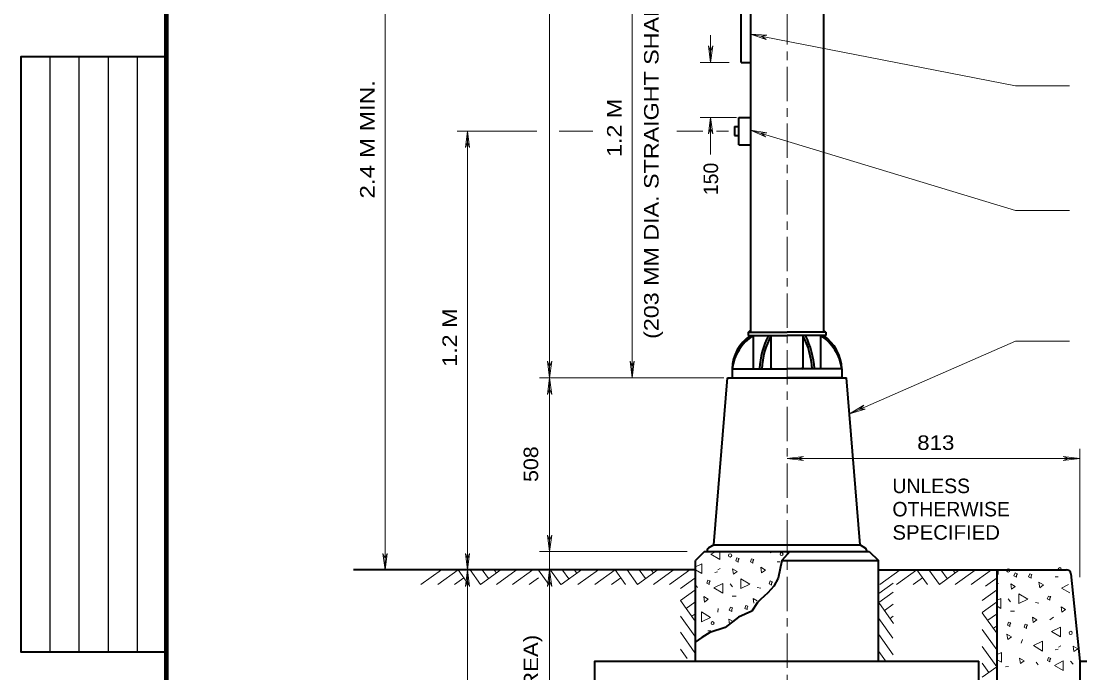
# Model space of a CAD drawing. Extents: x 312583 to 312853, y 144419 to 144586.
# Drawn here: x 312608.9 to 312664.4, y 144455.8 to 144490 of the extents above; entities that cross this region are included whole.
import ezdxf

# ---------------------------------------------------------------- set-up
doc = ezdxf.new("R2010")
doc.units = 0
doc.header["$LTSCALE"] = 0.3
doc.linetypes.add('LONG_DASH_SHORT_DASH', pattern=[9.9, 6, -1.2, 1.5, -1.2])
doc.layers.add('1', color=7, linetype='Continuous', lineweight=40)
doc.layers.add('2', color=7, linetype='Continuous', lineweight=13)

msp = doc.modelspace()

# ---------------------------------------------------------------- linework, layer by layer
at = {"layer": '1'}
for p, q in [((312647.0938, 144494.2759), (312647.0938, 144473.6679)), ((312650.9271, 144494.2759), (312650.9271, 144473.6679)), ((312646.6108, 144487.8053), (312646.6108, 144493.5553)), ((312646.6108, 144487.8053), (312647.0938, 144487.8053)), ((312646.4881, 144484.9303), (312647.0938, 144484.9303)), ((312646.4881, 144483.4966), (312646.4881, 144484.9303)), ((312646.2504, 144484.4549), (312646.2504, 144483.9719)), ((312646.2504, 144484.4549), (312646.4881, 144484.4549)), ((312646.2504, 144483.9719), (312646.4881, 144483.9719)), ((312646.4881, 144483.4966), (312647.0938, 144483.4966)), ((312646.9711, 144473.6679), (312649.0104, 144473.6679)), ((312646.9711, 144473.6679), (312646.9711, 144473.4916)), ((312651.0421, 144473.6679), (312649.0104, 144473.6679)), ((312651.0421, 144473.6679), (312651.0421, 144473.4916)), ((312646.9711, 144473.4916), (312649.0104, 144473.4916)), ((312647.2471, 144471.7513), (312647.2471, 144473.4916)), ((312648.1671, 144473.4916), (312648.1671, 144471.8126)), ((312651.0421, 144473.4916), (312649.0104, 144473.4916)), ((312649.8461, 144473.4916), (312649.8461, 144471.8126)), ((312650.7738, 144471.7513), (312650.7738, 144473.4916)), ((312646.1354, 144471.7513), (312649.0104, 144471.7513)), ((312646.1354, 144471.7513), (312646.1354, 144471.2759)), ((312651.8854, 144471.7513), (312649.0104, 144471.7513)), ((312651.8854, 144471.7513), (312651.8854, 144471.2759)), ((312645.1771, 144462.5283), (312645.8901, 144471.2759)), ((312645.8901, 144471.2759), (312652.1231, 144471.2759)), ((312646.1354, 144471.2759), (312649.0104, 144471.2759)), ((312651.8854, 144471.2759), (312649.0104, 144471.2759)), ((312652.8438, 144462.5283), (312652.1231, 144471.2759)), ((312645.1771, 144462.5283), (312644.8858, 144462.3443)), ((312645.1771, 144462.5283), (312652.8438, 144462.5283)), ((312652.8438, 144462.5283), (312653.1274, 144462.3443)), ((312644.6941, 144462.1679), (312644.2188, 144461.6926)), ((312644.6941, 144462.1679), (312653.3191, 144462.1679)), ((312653.3191, 144462.1679), (312653.8021, 144461.6926)), ((312644.2188, 144456.4179), (312644.2188, 144461.6926)), ((312648.7344, 144461.6926), (312653.8021, 144461.6926)), ((312653.8021, 144456.4179), (312653.8021, 144461.6926)), ((312644.2188, 144461.2096), (312626.2941, 144461.2096)), ((312653.8021, 144461.2096), (312663.6461, 144461.2096)), ((312660.0274, 144451.6263), (312660.0274, 144461.2096)), ((312663.8838, 144460.9949), (312664.3438, 144456.4179)), ((312664.3438, 144456.4179), (312664.3438, 144451.6263)), ((312664.3438, 144456.4179), (312717.6041, 144456.4179))]:
    msp.add_line(p, q, dxfattribs=at)
at = {"layer": '1', "lineweight": 25}
for p, q in [((312610.4087, 144456.901), (312610.4087, 144488.1192)), ((312611.9315, 144456.901), (312611.9315, 144488.1192)), ((312613.4543, 144456.901), (312613.4543, 144488.1192)), ((312614.9772, 144456.901), (312614.9772, 144488.1192)), ((312646.9711, 144473.6679), (312647.0938, 144473.7906)), ((312651.0421, 144473.6679), (312650.9271, 144473.7906))]:
    msp.add_line(p, q, dxfattribs=at)
at = {"layer": '1', "lineweight": 13}
for p, q in [((312660.0274, 144460.9949), (312660.0658, 144460.9643)), ((312660.0658, 144460.9643), (312660.0658, 144461.2096)), ((312663.0634, 144460.8416), (312663.2091, 144460.8493)), ((312660.0274, 144460.4583), (312660.0888, 144460.4966)), ((312660.6024, 144459.6916), (312660.7251, 144459.5383)), ((312660.0274, 144459.3083), (312660.2191, 144459.1933)), ((312662.0284, 144459.4999), (312662.2048, 144459.4616)), ((312660.7174, 144459.0399), (312660.9244, 144459.0476)), ((312662.9638, 144458.7333), (312662.7874, 144458.5953)), ((312661.3538, 144457.5526), (312661.2771, 144457.3763)), ((312663.0634, 144457.0159), (312663.2091, 144457.0466)), ((312663.2398, 144457.1539), (312663.3624, 144457.2229)), ((312660.0274, 144456.4946), (312660.2421, 144456.3643)), ((312662.0591, 144456.3643), (312662.1664, 144456.2263)), ((312663.8684, 144456.4179), (312663.9988, 144456.2646)), ((312660.4568, 144456.1266), (312660.6101, 144456.1419))]:
    msp.add_line(p, q, dxfattribs=at)
at = {"layer": '1', "lineweight": 158}
msp.add_lwpolyline([(312616.5, 144423.1446), (312616.5, 144585.0846), (312849, 144585.0846)], dxfattribs=at)
at = {"layer": '1', "lineweight": 35}
msp.add_lwpolyline([(312616.5, 144456.901), (312608.8858, 144456.901), (312608.8858, 144488.1192), (312616.5, 144488.1192)], dxfattribs=at)
at = {"layer": '1'}
for points in [[(312649.1638, 144462.1679), (312648.7344, 144461.6926), (312648.5428, 144460.7726), (312648.3128, 144460.3509), (312648.0061, 144460.0059), (312647.6228, 144459.6609), (312647.4694, 144459.5076), (312647.1628, 144459.0399), (312646.4651, 144458.7333), (312645.7751, 144458.1966), (312644.9624, 144457.9283), (312644.5408, 144457.6599), (312644.1958, 144457.4223)], [(312638.9441, 144439.1679), (312659.0691, 144439.1679), (312659.0691, 144456.4179)], [(312638.9441, 144439.1679), (312638.9441, 144456.4179), (312659.0691, 144456.4179)]]:
    msp.add_lwpolyline(points, dxfattribs=at)
at = {"layer": '1', "lineweight": 13}
for points in [[(312661.0318, 144460.9336), (312661.0778, 144461.0103), (312660.9628, 144461.0486), (312660.9014, 144460.8953), (312661.0318, 144460.8263)], [(312661.7984, 144460.8799), (312661.8444, 144460.9643), (312661.7294, 144460.9949), (312661.6681, 144460.8416), (312661.7984, 144460.7726)], [(312660.7788, 144460.1976), (312660.9704, 144460.3433), (312660.7328, 144460.4813)], [(312662.2508, 144460.2743), (312662.4501, 144460.4199), (312662.2124, 144460.5579)], [(312661.1621, 144459.9523), (312661.1621, 144459.4386), (312661.6298, 144459.6686)], [(312662.7798, 144459.7223), (312662.8258, 144459.8066), (312662.7108, 144459.8373), (312662.6494, 144459.6916), (312662.7798, 144459.6149)], [(312663.4161, 144458.9939), (312663.6078, 144459.1396), (312663.3778, 144459.2776)], [(312661.9134, 144458.4496), (312662.1051, 144458.5953), (312661.8751, 144458.7333)], [(312660.6868, 144458.3423), (312660.7328, 144458.4266), (312660.6178, 144458.4649), (312660.5564, 144458.3116), (312660.6868, 144458.2426)], [(312661.5608, 144458.2426), (312661.6068, 144458.3269), (312661.4918, 144458.3653), (312661.4304, 144458.2119), (312661.5608, 144458.1429)], [(312663.3394, 144457.6983), (312663.3394, 144458.2119), (312662.8718, 144457.9743)], [(312660.5718, 144457.5603), (312660.7634, 144457.7059), (312660.5334, 144457.8439)], [(312662.3964, 144456.9546), (312662.3964, 144457.4759), (312661.9288, 144457.2383)], [(312664.0448, 144456.9239), (312664.2441, 144457.0696), (312664.0064, 144457.2076)], [(312661.2388, 144456.2953), (312661.4304, 144456.4486), (312661.1928, 144456.5866)], [(312662.7874, 144456.4946), (312662.8334, 144456.5713), (312662.7184, 144456.6096), (312662.6571, 144456.4563), (312662.7874, 144456.3873)], [(312663.4851, 144455.9273), (312663.4851, 144456.4409), (312663.0174, 144456.2033)]]:
    msp.add_lwpolyline(points, close=True, dxfattribs=at)
for points in [[(312663.7534, 144460.4429), (312663.3931, 144460.2589), (312663.8224, 144460.0059)], [(312660.2191, 144459.1933), (312660.2191, 144459.7146), (312660.0274, 144459.6149)], [(312660.2421, 144456.3643), (312660.2421, 144456.8779), (312660.0274, 144456.7706)]]:
    msp.add_lwpolyline(points, dxfattribs=at)
for centre, radius in [((312663.2998, 144461.2478), 0.0784), ((312660.6003, 144461.1772), 0.0865), ((312663.8726, 144457.9049), 0.0865)]:
    msp.add_circle(centre, radius, dxfattribs=at)
at = {"layer": '1'}
for centre, radius, start, end in [((312648.3292, 144471.6731), 2.1986, 124.21849, 177.88724), ((312648.5437, 144471.4346), 2.4327, 122.28719, 172.4519), ((312652.0072, 144471.4976), 4.4452, 153.35491, 176.59885), ((312652.0072, 144471.4976), 4.3255, 152.55593, 176.59975), ((312646.007, 144471.4976), 4.3255, 3.40025, 27.44407), ((312646.007, 144471.4976), 4.4452, 3.40115, 26.64509), ((312649.4705, 144471.4346), 2.4327, 7.5481, 57.71281), ((312649.685, 144471.6731), 2.1986, 2.11276, 55.78151), ((312648.2284, 144471.814), 0.0599, 180, 270), ((312649.7857, 144471.814), 0.0599, 270, 0), ((312645.054, 144462.1708), 0.2396, 134.94464, 180), ((312652.9602, 144462.1708), 0.2396, 0, 45.05536), ((312663.6444, 144460.9729), 0.2396, 5.71059, 90)]:
    msp.add_arc(centre, radius, start, end, dxfattribs=at)
at = {"layer": '2', "linetype": 'LONG_DASH_SHORT_DASH'}
msp.add_line((312649.0104, 144438.2556), (312649.0104, 144579.5523), dxfattribs=at)
at = {"layer": '2'}
for p, q in [((312636.5751, 144471.2759), (312636.5751, 144564.8323)), ((312627.9501, 144461.2096), (312627.9501, 144507.2096)), ((312640.8914, 144471.2759), (312640.8914, 144494.2759)), ((312645.0084, 144487.8053), (312645.0084, 144489.2466)), ((312660.9781, 144486.5786), (312647.0938, 144489.2926)), ((312647.0938, 144489.2926), (312647.9218, 144489.0166)), ((312647.0938, 144489.2926), (312647.9601, 144489.2313)), ((312647.9601, 144489.2313), (312647.6688, 144489.1776)), ((312647.9218, 144489.0166), (312647.6688, 144489.1776)), ((312644.9011, 144488.6716), (312645.0084, 144488.3956)), ((312645.0084, 144487.8053), (312644.9011, 144488.6716)), ((312645.1158, 144488.6716), (312645.0084, 144488.3956)), ((312645.0084, 144487.8053), (312645.1158, 144488.6716)), ((312645.9744, 144487.8053), (312644.4641, 144487.8053)), ((312663.8071, 144486.5786), (312660.9781, 144486.5786)), ((312646.3578, 144484.9303), (312644.4641, 144484.9303)), ((312645.0084, 144484.9303), (312644.9011, 144484.0639)), ((312645.0084, 144482.9753), (312645.0084, 144484.9303)), ((312645.0084, 144484.9303), (312645.1158, 144484.0639)), ((312635.9004, 144484.2096), (312631.7221, 144484.2096)), ((312632.2664, 144484.2096), (312632.1591, 144483.3433)), ((312632.2664, 144461.2096), (312632.2664, 144484.2096)), ((312632.2664, 144484.2096), (312632.3738, 144483.3433)), ((312638.8444, 144484.2096), (312637.0734, 144484.2096)), ((312644.5944, 144484.2096), (312643.2374, 144484.2096)), ((312644.9011, 144484.0639), (312645.0084, 144484.3399)), ((312645.1158, 144484.0639), (312645.0084, 144484.3399)), ((312645.9514, 144484.2096), (312645.3151, 144484.2096)), ((312660.9781, 144480.0543), (312647.0938, 144484.2633)), ((312647.0938, 144484.2633), (312647.8911, 144483.9106)), ((312647.0938, 144484.2633), (312647.9524, 144484.1176)), ((312647.9524, 144484.1176), (312647.6534, 144484.0946)), ((312647.8911, 144483.9106), (312647.6534, 144484.0946)), ((312632.1591, 144483.3433), (312632.2664, 144483.6193)), ((312632.3738, 144483.3433), (312632.2664, 144483.6193)), ((312663.8071, 144480.0543), (312660.9781, 144480.0543)), ((312636.4678, 144472.1423), (312636.5751, 144471.8663)), ((312636.5751, 144471.2759), (312636.4678, 144472.1423)), ((312636.6824, 144472.1423), (312636.5751, 144471.8663)), ((312636.5751, 144471.2759), (312636.6824, 144472.1423)), ((312640.7841, 144472.1423), (312640.8914, 144471.8663)), ((312640.8914, 144471.2759), (312640.7841, 144472.1423)), ((312640.9988, 144472.1423), (312640.8914, 144471.8663)), ((312640.8914, 144471.2759), (312640.9988, 144472.1423)), ((312645.6984, 144471.2759), (312636.0461, 144471.2759)), ((312636.5751, 144471.2759), (312636.4678, 144470.4096)), ((312636.5751, 144462.1679), (312636.5751, 144471.2759)), ((312636.5751, 144471.2759), (312636.6824, 144470.4096)), ((312636.4678, 144470.4096), (312636.5751, 144470.6856)), ((312636.6824, 144470.4096), (312636.5751, 144470.6856)), ((312652.2764, 144469.3899), (312653.0278, 144469.8346)), ((312652.2764, 144469.3899), (312653.1121, 144469.6353)), ((312653.0278, 144469.8346), (312652.8208, 144469.6276)), ((312653.1121, 144469.6353), (312652.8208, 144469.6276)), ((312664.3438, 144460.8186), (312664.3438, 144467.5499)), ((312649.0104, 144467.0439), (312649.8768, 144467.1513)), ((312664.3438, 144467.0439), (312649.0104, 144467.0439)), ((312649.0104, 144467.0439), (312649.8768, 144466.9366)), ((312649.8768, 144467.1513), (312649.6008, 144467.0439)), ((312649.8768, 144466.9366), (312649.6008, 144467.0439)), ((312663.4774, 144467.1513), (312663.7534, 144467.0439)), ((312664.3438, 144467.0439), (312663.4774, 144467.1513)), ((312663.4774, 144466.9366), (312663.7534, 144467.0439)), ((312664.3438, 144467.0439), (312663.4774, 144466.9366)), ((312636.4678, 144463.0343), (312636.5751, 144462.7583)), ((312636.5751, 144462.1679), (312636.4678, 144463.0343)), ((312636.6824, 144463.0343), (312636.5751, 144462.7583)), ((312636.5751, 144462.1679), (312636.6824, 144463.0343)), ((312627.8428, 144462.0759), (312627.9501, 144461.7999)), ((312627.9501, 144461.2096), (312627.8428, 144462.0759)), ((312628.0574, 144462.0759), (312627.9501, 144461.7999)), ((312627.9501, 144461.2096), (312628.0574, 144462.0759)), ((312632.1591, 144462.0759), (312632.2664, 144461.7999)), ((312632.2664, 144461.2096), (312632.1591, 144462.0759)), ((312632.3738, 144462.0759), (312632.2664, 144461.7999)), ((312632.2664, 144461.2096), (312632.3738, 144462.0759)), ((312643.7818, 144462.1679), (312636.0461, 144462.1679)), ((312645.4914, 144461.7539), (312645.4914, 144462.1679)), ((312648.4891, 144461.6313), (312648.6348, 144461.6389)), ((312629.8284, 144460.4506), (312630.9018, 144461.2096)), ((312630.7101, 144460.4506), (312631.7834, 144461.2096)), ((312631.5918, 144460.4506), (312632.0748, 144460.7956)), ((312631.7834, 144461.2096), (312632.3201, 144460.4506)), ((312632.2664, 144461.2096), (312632.1591, 144460.3433)), ((312632.2664, 144439.1679), (312632.2664, 144461.2096)), ((312632.2664, 144461.2096), (312632.3738, 144460.3433)), ((312632.4044, 144461.2096), (312632.9488, 144460.4506)), ((312632.9488, 144460.4506), (312634.0374, 144461.2249)), ((312633.0331, 144461.2096), (312633.3628, 144460.7496)), ((312633.6618, 144461.2096), (312633.7844, 144461.0409)), ((312633.7844, 144460.4506), (312634.8194, 144461.1943)), ((312634.6201, 144460.4506), (312635.6934, 144461.2096)), ((312635.5018, 144460.4506), (312635.9924, 144460.7956)), ((312635.9924, 144461.2019), (312636.5291, 144460.4429)), ((312636.5751, 144461.2096), (312636.4678, 144460.3433)), ((312636.5751, 144461.2096), (312636.6824, 144460.3433)), ((312636.6134, 144461.2019), (312637.1578, 144460.4429)), ((312637.1731, 144460.4506), (312638.2464, 144461.2096)), ((312637.2421, 144461.2019), (312637.5794, 144460.7343)), ((312637.8708, 144461.2019), (312637.9934, 144461.0333)), ((312638.0548, 144460.4506), (312639.1281, 144461.2096)), ((312638.9364, 144460.4506), (312640.0098, 144461.2096)), ((312639.8181, 144460.4506), (312640.3011, 144460.7956)), ((312640.0098, 144461.2096), (312640.5464, 144460.4506)), ((312640.6308, 144461.2096), (312641.1751, 144460.4506)), ((312641.1751, 144460.4506), (312642.2638, 144461.2249)), ((312641.2594, 144461.2096), (312641.5891, 144460.7496)), ((312641.8881, 144461.2096), (312642.0108, 144461.0409)), ((312642.0108, 144460.4506), (312643.0458, 144461.1943)), ((312642.8464, 144460.4506), (312643.9198, 144461.2096)), ((312644.1881, 144460.7803), (312643.4291, 144460.2359)), ((312644.2188, 144461.2173), (312644.5484, 144461.0179)), ((312645.2231, 144461.0793), (312645.3688, 144461.1023)), ((312645.3918, 144461.2096), (312645.5144, 144461.2786)), ((312653.8711, 144460.4506), (312654.9368, 144461.2096)), ((312654.7528, 144460.4506), (312655.8184, 144461.2096)), ((312655.6268, 144460.4506), (312656.1174, 144460.7956)), ((312655.8184, 144461.2096), (312656.3628, 144460.4506)), ((312656.4471, 144461.2096), (312656.9914, 144460.4506)), ((312656.9914, 144460.4506), (312658.0724, 144461.2249)), ((312657.0758, 144461.2096), (312657.4054, 144460.7496)), ((312657.7044, 144461.2096), (312657.8194, 144461.0409)), ((312657.8194, 144460.4506), (312658.8621, 144461.1943)), ((312658.6628, 144460.4506), (312659.7284, 144461.2096)), ((312659.4064, 144460.3586), (312660.0274, 144460.7956)), ((312632.1591, 144460.3433), (312632.2664, 144460.6193)), ((312632.3738, 144460.3433), (312632.2664, 144460.6193)), ((312636.4678, 144460.3433), (312636.5751, 144460.6193)), ((312636.6824, 144460.3433), (312636.5751, 144460.6193)), ((312644.2188, 144460.4199), (312644.3184, 144460.2819)), ((312646.0281, 144460.4813), (312646.1508, 144460.3203)), ((312647.4541, 144460.2896), (312647.6304, 144460.2436)), ((312654.5764, 144460.5196), (312653.8174, 144459.9753)), ((312644.1881, 144460.1516), (312643.4291, 144459.6073)), ((312646.1431, 144459.8296), (312646.3501, 144459.8373)), ((312654.5764, 144460.0366), (312653.8174, 144459.4923)), ((312659.9891, 144460.1516), (312659.2301, 144459.6073)), ((312643.4291, 144459.6073), (312644.2034, 144458.5263)), ((312644.1881, 144459.5229), (312643.7281, 144459.1933)), ((312645.3841, 144458.9939), (312645.4071, 144459.1856)), ((312653.8174, 144459.4923), (312654.5918, 144458.4036)), ((312654.5764, 144459.4079), (312654.1088, 144459.0706)), ((312659.9891, 144459.5229), (312659.2301, 144458.9786)), ((312643.4291, 144458.7793), (312644.1728, 144457.7366)), ((312644.1881, 144458.8943), (312644.0194, 144458.7793)), ((312653.8174, 144458.6566), (312654.5534, 144457.6216)), ((312654.5764, 144458.7793), (312654.4078, 144458.6566)), ((312659.2378, 144458.9633), (312660.0044, 144457.8976)), ((312659.9891, 144458.8943), (312659.5291, 144458.5646)), ((312644.8704, 144458.0126), (312645.0161, 144458.0203)), ((312659.2378, 144458.0816), (312660.0044, 144457.0159)), ((312659.9891, 144458.2656), (312659.8204, 144458.1506)), ((312643.4291, 144457.9359), (312644.1881, 144456.8626)), ((312653.8174, 144457.8133), (312654.5764, 144456.7476)), ((312643.4291, 144457.0543), (312643.7741, 144456.5713)), ((312653.8174, 144456.9393), (312654.1624, 144456.4486)), ((312659.2378, 144457.1999), (312660.0044, 144456.1343)), ((312659.2378, 144456.3259), (312659.5904, 144455.8353)), ((312660.0044, 144456.1343), (312659.2378, 144455.5899))]:
    msp.add_line(p, q, dxfattribs=at)
for points in [[(312663.8071, 144473.1926), (312660.9781, 144473.1926), (312652.2764, 144469.3899)], [(312636.5751, 144443.7373), (312636.5751, 144461.2096), (312636.5751, 144462.1679)], [(312645.2998, 144462.1679), (312645.0238, 144462.0376), (312645.4914, 144461.7539)], [(312648.1518, 144462.1679), (312648.1518, 144462.0989), (312648.2974, 144462.1679)], [(312644.5484, 144461.0179), (312644.5484, 144461.5316), (312644.2188, 144461.3629)], [(312647.4541, 144459.5843), (312647.2318, 144459.7146), (312647.2701, 144459.4693)], [(312644.2188, 144457.5603), (312644.2571, 144457.5909), (312644.2188, 144457.6139)]]:
    msp.add_lwpolyline(points, dxfattribs=at)
for points in [[(312646.4574, 144461.7233), (312646.5034, 144461.7999), (312646.3884, 144461.8383), (312646.3271, 144461.6849), (312646.4574, 144461.6159)], [(312647.2241, 144461.6696), (312647.2701, 144461.7463), (312647.1551, 144461.7846), (312647.0938, 144461.6313), (312647.2241, 144461.5623)], [(312647.6764, 144461.0563), (312647.8758, 144461.2019), (312647.6381, 144461.3476)], [(312646.2044, 144460.9796), (312646.3961, 144461.1253), (312646.1584, 144461.2709)], [(312644.9394, 144460.5503), (312644.9854, 144460.6346), (312644.8704, 144460.6653), (312644.8091, 144460.5119), (312644.9394, 144460.4429)], [(312645.6448, 144459.9829), (312645.6448, 144460.4966), (312645.1771, 144460.2666)], [(312646.5878, 144460.7419), (312646.5878, 144460.2283), (312647.0554, 144460.4583)], [(312648.2054, 144460.5119), (312648.2514, 144460.5886), (312648.1364, 144460.6269), (312648.0751, 144460.4736), (312648.2054, 144460.4046)], [(312644.6941, 144459.5229), (312644.8858, 144459.6686), (312644.6558, 144459.8066)], [(312646.1124, 144459.1319), (312646.1584, 144459.2163), (312646.0434, 144459.2469), (312645.9821, 144459.0936), (312646.1124, 144459.0246)], [(312646.9174, 144459.2239), (312646.9634, 144459.3083), (312646.8484, 144459.3466), (312646.7948, 144459.1933), (312646.9174, 144459.1243)], [(312644.5331, 144459.0016), (312644.5331, 144458.4803), (312645.0008, 144458.7179)], [(312645.9974, 144458.3499), (312646.1891, 144458.4956), (312645.9591, 144458.6336)]]:
    msp.add_lwpolyline(points, close=True, dxfattribs=at)
for centre, radius in [((312646.0259, 144461.9639), 0.0865), ((312648.7254, 144462.0346), 0.0784), ((312645.1082, 144458.4173), 0.0784)]:
    msp.add_circle(centre, radius, dxfattribs=at)

# ---------------------------------------------------------------- texts
for s, width, p in [('(203 MM DIA. STRAIGHT SHAFT)', 1.2, (312642.2801, 144473.3174)), ('2.4 M MIN.', 1.25, (312627.3997, 144480.6731)), ('1.2 M', 1.2, (312640.341, 144482.8537)), ('1.2 M', 1.2, (312631.716, 144471.8557)), ('508', 1.1, (312635.971, 144465.8195)), ('25 (IN SIDEWALK AREA)', 1.15, (312635.9709, 144444.362))]:
    msp.add_text(s, height=0.76, rotation=90, dxfattribs=dict(at, width=width)).set_placement(p)
msp.add_text('150', height=0.76, rotation=90, dxfattribs=at).set_placement((312645.3969, 144480.8551))
for s, width, p in [('813 ', 1.15, (312655.8306, 144467.4991)), ('SPECIFIED', 1.05, (312654.5339, 144462.7918))]:
    msp.add_text(s, height=0.76, dxfattribs=dict(at, width=width)).set_placement(p)
for s, p in [('UNLESS', (312654.5339, 144465.2318)), ('OTHERWISE', (312654.5339, 144464.0118))]:
    msp.add_text(s, height=0.76, dxfattribs=at).set_placement(p)

doc.saveas('drawing.dxf')
